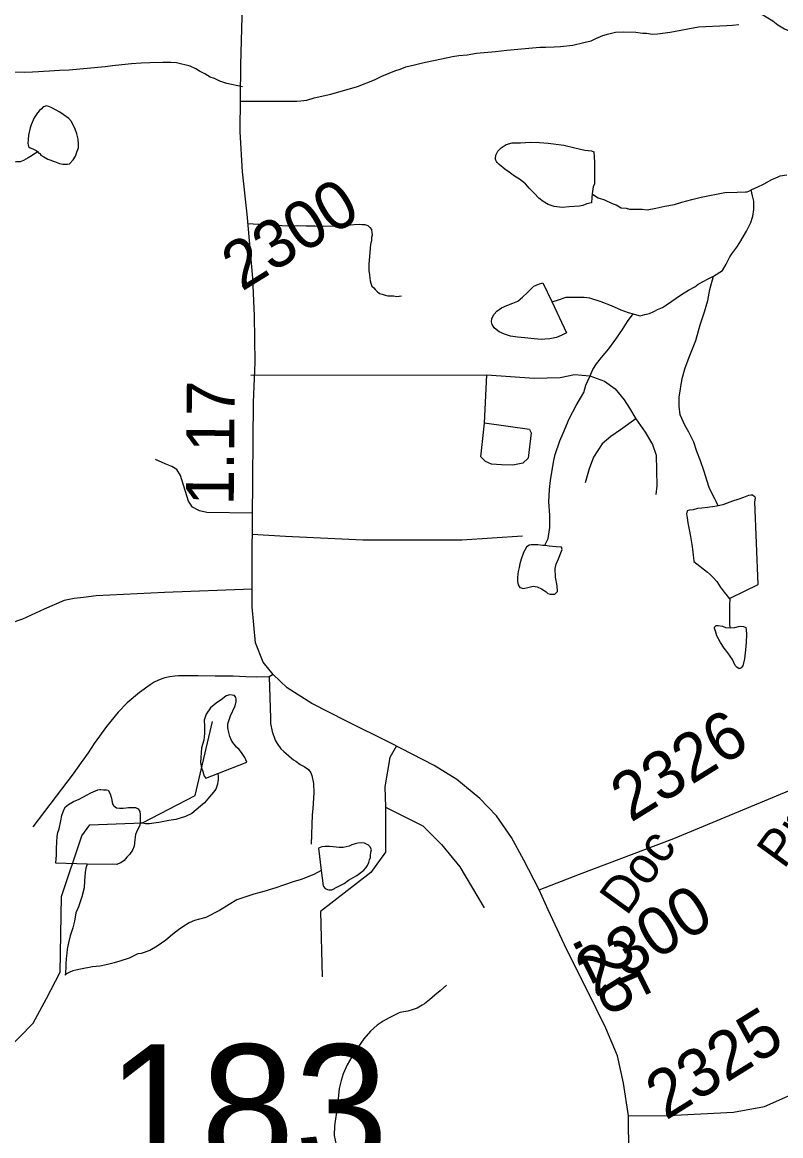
# Model space of a CAD drawing. Extents: x 2001466 to 31450019, y -30647475 to 847247.
# Drawn here: x 2175250 to 2179202, y 755442 to 761240 of the extents above; entities that cross this region are included whole.
import ezdxf

# ---------------------------------------------------------------- set-up
doc = ezdxf.new("R2010")
doc.units = 0
for name, color, linetype in [('Exist Hydrographic Misc Water Feature', 7, 'Continuous'), ('Exist Road Non-System Type 51', 7, 'Continuous'), ('Exist Road Secondary Mileage Hundredths English Label', 7, 'Continuous'), ('Exist Road Secondary Structure Standard Bridge Number Label', 7, 'Continuous'), ('Exist Road Secondary Type 51 Attributed', 7, 'Continuous'), ('Exist Road Secondary Type 51 Label', 7, 'Continuous'), ('Exist Road Secondary Type 51 Number Label', 7, 'Continuous')]:
    doc.layers.add(name, color=color, linetype=linetype)

msp = doc.modelspace()

# ---------------------------------------------------------------- linework, layer by layer
at = {"layer": 'Exist Hydrographic Misc Water Feature'}
for points in [[(2179000.1, 761330.1), (2179013.9, 761326.4), (2179037.8, 761314.7), (2179080.1, 761292.9), (2179118, 761273), (2179160.5, 761247.1), (2179188.1, 761227.5), (2179222.8, 761205.6), (2179250.5, 761193.7), (2179284.3, 761180), (2179328.6, 761162), (2179381.1, 761140.3), (2179474.8, 761090.8), (2179511.3, 761075.2), (2179547, 761069.4), (2179582.9, 761063.6), (2179603.2, 761059.7), (2179637.2, 761048)], [(2175331.5, 760565.9), (2175337.3, 760557.7), (2175341.4, 760555.9), (2175347.7, 760548), (2175363.3, 760540), (2175383.4, 760528), (2175417.6, 760514.3), (2175444.1, 760504.7), (2175462.1, 760500.7), (2175472, 760500.4), (2175485.9, 760500.8), (2175495.8, 760503), (2175515.7, 760523.1), (2175527.4, 760543.2), (2175537.2, 760568.9), (2175543.3, 760587), (2175543.3, 760604.9), (2175541.3, 760631.1), (2175534.7, 760658.9), (2175524.5, 760688.8), (2175508.7, 760718.8), (2175506.8, 760722.7), (2175492.5, 760738.7), (2175464.2, 760760.4), (2175446.1, 760772.4), (2175403.9, 760794.3), (2175388.1, 760801.9), (2175374.2, 760804.1), (2175367.8, 760802.2), (2175359.8, 760800.1), (2175350.2, 760789.8), (2175340.3, 760779.9), (2175330.3, 760767.7), (2175316.4, 760747.9), (2175312.3, 760741.6), (2175296.5, 760705.4), (2175290.9, 760689.7), (2175282.9, 760651.5), (2175280.9, 760629.5), (2175278.8, 760609.5), (2175281.3, 760601.5), (2175283.3, 760593.4), (2175291.5, 760585.7), (2175305.3, 760581.6), (2175309.6, 760579.8), (2175323.1, 760572), (2175331.5, 760565.9)], [(2178219.7, 760346.4), (2178217.8, 760328.4), (2178215.8, 760300.3), (2178192.2, 760294.1), (2178172.1, 760285.8), (2178154.1, 760282), (2178100.1, 760279.6), (2178064, 760275.3), (2178022.2, 760280.8), (2177990.2, 760290.9), (2177964, 760306.7), (2177941.8, 760324.6), (2177917.6, 760350.6), (2177891.4, 760376.5), (2177871.7, 760398.1), (2177841.2, 760422.2), (2177815.3, 760437.9), (2177787, 760459.6), (2177765.1, 760475.5), (2177735.1, 760499.5), (2177724.9, 760509.2), (2177720.8, 760515.5), (2177716.9, 760525.4), (2177716.7, 760529.5), (2177718.5, 760547.5), (2177728.6, 760569.4), (2177746.4, 760585.4), (2177772.5, 760603.4), (2177802.2, 760611.8), (2177846.1, 760612.1), (2177898.2, 760616.4), (2177946.3, 760614.4), (2177990.4, 760611), (2178072.3, 760599.4), (2178130.3, 760585.8), (2178182.2, 760573.9), (2178216.4, 760569.9), (2178228.1, 760566.1), (2178230.6, 760540.2), (2178232.8, 760510.2), (2178231.2, 760446.4), (2178231.2, 760398.1), (2178225.6, 760382.3), (2178219.7, 760346.4)], [(2175331.5, 760565.9), (2175309.6, 760551.8), (2175301.8, 760545.6), (2175281.5, 760533.7), (2175257.5, 760519.5), (2175239.9, 760513.2), (2175220, 760513.4), (2175203.8, 760511), (2175174, 760511), (2175145.7, 760516.9), (2175109.9, 760528.8), (2175087.3, 760536.7), (2175063.5, 760536.2), (2175045.5, 760538.1), (2175033.6, 760538.3), (2175029.9, 760538.1)], [(2179047.5, 760366.9), (2179067, 760376.9), (2179079.1, 760381.1), (2179115.4, 760399.2), (2179156.8, 760421.3), (2179189, 760435.5), (2179199, 760439.6), (2179234.9, 760446)], [(2178219.7, 760346.4), (2178231.4, 760338.5), (2178251.9, 760326.5), (2178284.1, 760314.7), (2178324.1, 760296.9), (2178345.6, 760288.8), (2178371.8, 760273), (2178396.2, 760271.4), (2178414.3, 760267.4), (2178461.9, 760267.5), (2178480.1, 760267.6), (2178506.3, 760263.7), (2178551.9, 760272.2), (2178597.8, 760282.3), (2178649.7, 760290.6), (2178687.8, 760302.7), (2178739.5, 760317.2), (2178787.5, 760329.4), (2178911.5, 760354.1), (2178975.1, 760356.2), (2179019.4, 760356.5), (2179027.6, 760356.9), (2179035.4, 760361), (2179047.5, 760366.9)], [(2178852.1, 759917.7), (2178899.6, 759948.2), (2178917.7, 759980), (2178937.6, 760018.4), (2178947, 760034.4), (2178973, 760068.6), (2178989, 760092.5), (2179024.5, 760152.9), (2179046.5, 760197), (2179057.9, 760231), (2179061.8, 760264.8), (2179061.8, 760294.9), (2179061.6, 760308.7), (2179055.3, 760336.9), (2179047.5, 760366.9)], [(2178432.9, 759721.4), (2178439.1, 759719.7), (2178469.2, 759711.9), (2178494.9, 759717.8), (2178518.9, 759724.3), (2178541, 759734.3), (2178560.9, 759744.3), (2178586.7, 759754.6), (2178607, 759768.6), (2178684.5, 759823), (2178722.3, 759845.3), (2178754, 759863.1), (2178772.3, 759875.4), (2178797.9, 759889.8), (2178823.8, 759903.7), (2178845.7, 759913.8), (2178852.1, 759917.7)], [(2178876.5, 758722.2), (2178866.2, 758744.4), (2178858.2, 758758.2), (2178832, 758812.1), (2178818, 758856), (2178803.7, 758899.9), (2178785.2, 758955.8), (2178765.1, 759005.5), (2178748.9, 759053.4), (2178724.3, 759105.4), (2178702.4, 759141.2), (2178678.2, 759195.1), (2178673.9, 759241.2), (2178673.5, 759287.1), (2178688.8, 759385), (2178704.6, 759441), (2178728, 759505.2), (2178759.8, 759583.6), (2178783.4, 759663.6), (2178804.9, 759731.8), (2178822.5, 759791.5), (2178832.2, 759847.7), (2178852.1, 759917.7)], [(2178008.9, 759785.1), (2178085.6, 759623.4), (2178057.7, 759609.4), (2178033.9, 759599.2), (2177999.9, 759591.3), (2177974, 759589.2), (2177954.1, 759588.9), (2177899.8, 759592.7), (2177868.2, 759596.3), (2177830.3, 759600.4), (2177794.2, 759605.8), (2177763.9, 759615.6), (2177735.8, 759627.6), (2177720, 759639.8), (2177709.9, 759649.4), (2177699.5, 759665.6), (2177695.6, 759679.6), (2177697.6, 759697.5), (2177709.3, 759719.7), (2177723, 759735.4), (2177747, 759753.8), (2177775.3, 759765.6), (2177807.1, 759777.9), (2177832.5, 759788.3), (2177856.7, 759808.1), (2177882.4, 759832.6), (2177896.7, 759846.3), (2177916.6, 759866.4), (2177940.4, 759876.6), (2177962.3, 759883), (2178008.9, 759785.1)], [(2178008.9, 759785.1), (2178016.9, 759785.1), (2178045, 759795.5), (2178084.8, 759807.7), (2178122.7, 759807.7), (2178178.9, 759808.1), (2178206.8, 759804.3), (2178265, 759786.6), (2178318.7, 759765.1), (2178369, 759743.2), (2178407.1, 759729.4), (2178432.9, 759721.4)], [(2177974.2, 758515.4), (2177975.9, 758523.2), (2177990, 758551.5), (2177999.7, 758609.3), (2177998.8, 758673.5), (2177994.7, 758743.5), (2177998.2, 758807.5), (2178002.1, 758853.6), (2178009.7, 758897.4), (2178019.3, 758957.6), (2178027.3, 758989.7), (2178050.7, 759059.5), (2178068.6, 759099.9), (2178100.3, 759175.8), (2178135.8, 759243.8), (2178175.8, 759312.1), (2178187.3, 759350.5), (2178207, 759394.6), (2178223, 759432.3), (2178242.4, 759460.6), (2178268.3, 759494.8), (2178306.2, 759539), (2178343.9, 759589.2), (2178377.8, 759639.3), (2178403.4, 759681.3), (2178432.9, 759721.4)], [(2178939.2, 758240.9), (2179084.8, 758311.8), (2179068.2, 758743.5), (2179070.4, 758761.5), (2179070, 758769.6), (2179063.9, 758771.3), (2179056.1, 758777.4), (2179047.9, 758777.4), (2179034.2, 758775.4), (2179008.1, 758765.1), (2178978.4, 758755), (2178950.3, 758746.7), (2178900.7, 758726.6), (2178876.5, 758722.2)], [(2178876.5, 758722.2), (2178858.8, 758718.4), (2178820.3, 758714), (2178790.8, 758710), (2178768.6, 758707.7), (2178746.5, 758701.7), (2178727, 758699.4), (2178714.7, 758695.5), (2178710.8, 758679.5), (2178714.7, 758659.4), (2178719, 758633.7), (2178725.1, 758599.4), (2178731.5, 758561.5), (2178739.9, 758519.7), (2178743.8, 758481.8), (2178745.8, 758463.7), (2178748.1, 758453.6), (2178750.4, 758431.7), (2178820.5, 758376.1), (2178836.5, 758362.3), (2178852.7, 758346.5), (2178868.7, 758328.6), (2178886.5, 758300.8), (2178907, 758272.6), (2178922.8, 758252.7), (2178929.2, 758246.9), (2178935.5, 758237), (2178939.2, 758240.9)], [(2177974.2, 758515.4), (2177962.3, 758515.1), (2177936.1, 758519.1), (2177920.1, 758519.1), (2177902.1, 758519), (2177892, 758516.9), (2177878.1, 758506.8), (2177862.3, 758478.7), (2177850.4, 758444.9), (2177842.4, 758420.5), (2177838.7, 758400.8), (2177835, 758380.7), (2177832.5, 758366.8), (2177831.3, 758348.8), (2177830.9, 758328.5), (2177833.6, 758310.7), (2177843.4, 758296.6), (2177861.3, 758290.7), (2177891.4, 758299.1), (2177913.3, 758303.1), (2177933.2, 758299.3), (2177955.4, 758289.5), (2177969.3, 758281.3), (2177979.4, 758273.6), (2177989.6, 758265.6), (2178001.3, 758261.4), (2178025.5, 758261.8), (2178039.2, 758275.9), (2178037.2, 758305.9), (2178028.6, 758349.8), (2178026.5, 758395.5), (2178032.3, 758417.7), (2178044.4, 758446), (2178060.2, 758485.8), (2178064.3, 758494.1), (2178060.2, 758506.1), (2178032.1, 758507.9), (2177996, 758511.3), (2177974.2, 758515.4)], [(2178938.2, 758086.9), (2178938, 758108.9), (2178938, 758126.7), (2178937.6, 758154.8), (2178937.6, 758180.7), (2178937.6, 758210.8), (2178939.2, 758228.8), (2178939.2, 758240.9)], [(2178938.2, 758086.9), (2178964, 758089.1), (2178982.1, 758093.3), (2178992.3, 758095.4), (2179008.1, 758093.4), (2179019.8, 758087.6), (2179022.1, 758077.5), (2179024.5, 758051.6), (2179022.5, 758009.3), (2179018.8, 757971.3), (2179013.2, 757925.5), (2179005, 757889.4), (2178995.4, 757877.5), (2178985.3, 757873.3), (2178973.3, 757881.3), (2178965, 757891), (2178951.3, 757921), (2178927.1, 757956.8), (2178908.5, 757980.7), (2178888.4, 758010.5), (2178870.3, 758044.5), (2178864.2, 758064.4), (2178857.8, 758084.5), (2178858, 758090.5), (2178866.2, 758098.6), (2178875.9, 758098.8), (2178898.2, 758094.6), (2178913.8, 758089), (2178938.2, 758086.9)], [(2176269.2, 757328.2), (2176421, 757386.8), (2176410.9, 757411), (2176392.7, 757436.9), (2176380.6, 757452.9), (2176366.2, 757464.8), (2176354.5, 757480.4), (2176342.2, 757496.4), (2176332.2, 757520.3), (2176326, 757542.3), (2176321.9, 757566.4), (2176321.9, 757586.3), (2176335.7, 757628.4), (2176347.4, 757654.7), (2176359.2, 757680.5), (2176365.2, 757702.7), (2176364.8, 757716.5), (2176363.1, 757724.5), (2176356.8, 757734.4), (2176332.8, 757738.4), (2176313.1, 757732.4), (2176293, 757716), (2176260.8, 757694.1), (2176231.3, 757669.8), (2176209.4, 757637.8), (2176197.7, 757605.9), (2176199.9, 757573.5), (2176200.1, 757535.8), (2176196, 757501.5), (2176184.7, 757461.8), (2176178.8, 757385.7), (2176185.2, 757357.5), (2176191.3, 757337.9), (2176195.2, 757325.6), (2176199.1, 757313.6), (2176207.3, 757303.8), (2176269.2, 757328.2)], [(2175376.3, 756156.9), (2175448, 756293.4), (2175454.1, 756686.9), (2175561.2, 757002.9), (2175602, 757061.1), (2175877.2, 757071.8), (2176151.1, 757213.8), (2176241.1, 757599.1)], [(2176269.2, 757328.2), (2176271.3, 757310), (2176271.1, 757294.2), (2176269.8, 757286.3), (2176267.6, 757272.1), (2176259.8, 757246), (2176246.1, 757229.9), (2176226, 757206.1), (2176200.1, 757175.9), (2176180, 757157.9), (2176134.5, 757119.3), (2176100.9, 757103.3), (2176050.4, 757089), (2176014.6, 757082.7), (2175962.7, 757072.7), (2175948.7, 757070.3), (2175912.8, 757066), (2175892.8, 757066.2), (2175876.8, 757069.9), (2175864.9, 757072.1)], [(2175588, 756856.3), (2175426.1, 756861.3), (2175428.1, 756903.6), (2175428.1, 756939.4), (2175431.6, 757001.3), (2175435.3, 757021.4), (2175443.1, 757039.7), (2175450.9, 757081.5), (2175456.8, 757109.8), (2175466.4, 757139.6), (2175476.5, 757153.9), (2175492.1, 757165.7), (2175518.1, 757182.1), (2175546.4, 757194), (2175566.1, 757204.1), (2175588, 757216.1), (2175607.9, 757226.5), (2175620, 757232.4), (2175643.8, 757242.6), (2175653.9, 757244.7), (2175659.8, 757244.6), (2175673.6, 757242.9), (2175689.8, 757242.9), (2175698, 757240.9), (2175707.8, 757221.2), (2175714.2, 757205.2), (2175716.4, 757189), (2175718.3, 757177), (2175722.1, 757167.1), (2175726.3, 757161.2), (2175734.2, 757155.1), (2175742.2, 757149.4), (2175756.4, 757147.3), (2175776.3, 757147.5), (2175792.3, 757149.5), (2175804.2, 757151.4), (2175816.1, 757151.6), (2175832.3, 757151.6), (2175840.3, 757151.6), (2175854.4, 757143.8), (2175862.6, 757130), (2175864.7, 757113.9), (2175864.9, 757079.8), (2175864.9, 757072.1)], [(2175864.9, 757072.1), (2175863, 757057.8), (2175851.3, 757033.9), (2175840.9, 757009.9), (2175837.6, 756981.7), (2175833.5, 756949.9), (2175825.5, 756927.9), (2175809.9, 756905.5), (2175795.8, 756891.5), (2175782, 756875.7), (2175763.8, 756863.4), (2175750, 756857.4), (2175743.9, 756853.4), (2175588, 756856.3)], [(2176807.7, 756823.2), (2176818.2, 756743.4), (2176820.4, 756739.4), (2176828.2, 756729.7), (2176840.3, 756723.4), (2176848.5, 756721.7), (2176862.6, 756721.6), (2176892.6, 756737.8), (2176928.3, 756755.9), (2176950, 756772.1), (2176994.1, 756796.3), (2177007.6, 756806.4), (2177029.8, 756824.6), (2177041.9, 756838.6), (2177049.5, 756848.8), (2177055.6, 756864.9), (2177059.7, 756878.9), (2177065.4, 756890.6), (2177065.4, 756900.8), (2177067.1, 756918.8), (2177069.5, 756931), (2177062.8, 756946.9), (2177054.8, 756954.7), (2177041.2, 756962.4), (2177033, 756964.4), (2177018.9, 756966.6), (2176999, 756964.3), (2176985.1, 756962.4), (2176967, 756956.2), (2176952.9, 756950.2), (2176923.1, 756942.1), (2176901.4, 756941.8), (2176871.1, 756945.6), (2176851.4, 756947.7), (2176829.2, 756947.4), (2176811.4, 756945.2), (2176793.3, 756939), (2176807.7, 756823.2)], [(2175588, 756856.3), (2175582.3, 756834.5), (2175578.6, 756812.3), (2175574.7, 756768.3), (2175572.9, 756732.5), (2175561, 756686.4), (2175543.3, 756634.3), (2175529.6, 756602.3), (2175521.8, 756558.1), (2175514, 756523.9), (2175500.3, 756482.2), (2175490.9, 756445.9), (2175484.7, 756414), (2175482.6, 756392), (2175479, 756364.1), (2175477.1, 756336), (2175477.1, 756320.2), (2175475.3, 756292.1), (2175473.4, 756278.2)], [(2176807.7, 756823.2), (2176770, 756801.4), (2176704.3, 756776.8), (2176662.3, 756764.5), (2176612.1, 756746.1), (2176572.3, 756731.9), (2176508.5, 756713.5), (2176456.9, 756699.4), (2176404.8, 756682.9), (2176368.9, 756670.9), (2176329.1, 756646.5), (2176277.4, 756614.2), (2176207.7, 756578.1), (2176173.5, 756569.9), (2176147.4, 756561.6), (2176119.5, 756549.6), (2176087.8, 756529.3), (2176063.8, 756513.4), (2176033.8, 756489.2), (2175998.6, 756460.8), (2175954.1, 756428.6), (2175914.7, 756406.6), (2175870.8, 756390.1), (2175852.6, 756388), (2175806.8, 756366.1), (2175758.9, 756351.4), (2175729.1, 756341.3), (2175687.1, 756331), (2175655.1, 756324.9), (2175617, 756320.9), (2175553.2, 756308.3), (2175529.2, 756304.2), (2175513.2, 756300.1), (2175499.1, 756294.2), (2175481.2, 756284.3), (2175473.4, 756278.2)], [(2177461.2, 756225.1), (2177427.2, 756197), (2177399.3, 756172.8), (2177371.6, 756148.6), (2177345.5, 756128.6), (2177333.7, 756120.7), (2177308, 756106.3), (2177281.6, 756096.5), (2177259.8, 756090.1), (2177218, 756083.8), (2177190.1, 756069.8), (2177162.2, 756055.7), (2177130.2, 756037.4), (2177100.1, 756017.2), (2177064.4, 755986.9), (2177030.6, 755947), (2176979.1, 755872.5), (2176943.8, 755810.4), (2176922.1, 755764.3), (2176912.3, 755728.4), (2176902.2, 755688.2), (2176896.5, 755634.3), (2176890.9, 755582.4), (2176885, 755542.3), (2176877.6, 755492.3), (2176875.6, 755442.3), (2176885.8, 755394.1)], [(2174048.1, 755003.3), (2174180.2, 755187.6), (2174354, 755321.8), (2174586.2, 755546.7), (2174802.1, 755683.3), (2175085.1, 755802.1), (2175308.1, 756027.2), (2175376.3, 756156.9)]]:
    msp.add_lwpolyline(points, dxfattribs=at)
at = {"layer": 'Exist Road Non-System Type 51'}
for p, q in [((2176441.8, 759402.7), (2177670.6, 759404.4)), ((2177658.7, 759152.6), (2177670.6, 759404.4)), ((2177894.1, 759119.2), (2177658.7, 759152.6)), ((2176557, 757843.4), (2176536.2, 757830.6))]:
    msp.add_line(p, q, dxfattribs=at)
for points in [[(2176391.6, 760829.7), (2176680.3, 760829.6), (2176702.4, 760831.1), (2176732.4, 760834.7), (2176770.7, 760845.9), (2176858.9, 760866.5), (2176997.7, 760906.3), (2177086.2, 760940.6), (2177124.5, 760960), (2177162.9, 760975.5), (2177191.1, 760986.9), (2177219.3, 760996.5), (2177249.3, 761008.1), (2177293.5, 761019.2), (2177335.7, 761028.5), (2177492.4, 761061.9), (2177524.5, 761067.4), (2177568.6, 761070.7), (2177616.7, 761079.9), (2177716.9, 761088.1), (2177775, 761095.3), (2177947.3, 761110.4), (2177979.3, 761109.7), (2178021.4, 761113), (2178055.4, 761114.5), (2178119.5, 761121.4), (2178176.2, 761134.9), (2178214, 761143.9), (2178238.2, 761155.4), (2178276.3, 761170.8), (2178306.5, 761180.4), (2178340.7, 761187.7), (2178382.7, 761191), (2178446.6, 761187.9), (2178470.8, 761185.6), (2178484.7, 761183.3), (2178502.7, 761183), (2178534.6, 761178.5), (2178560.7, 761180), (2178626.8, 761189), (2178773.4, 761216.4), (2178921.5, 761224), (2178951.5, 761225.6), (2178983.6, 761228.9)], [(2176397.5, 760904.2), (2176315.7, 760921.6), (2176279.9, 760934.2), (2176252, 760946.7), (2176230.2, 760955), (2176202.5, 760971.5), (2176174.6, 760985.9), (2176154.9, 760998.3), (2176125.1, 761010.9), (2176053.3, 761028), (2176025.3, 761030.6), (2175983.4, 761031.2), (2175915.3, 761028.4), (2175869.3, 761027.2), (2175819.2, 761024), (2175769.1, 761018.8), (2175721, 761013.6), (2175682.9, 761008.2), (2175494.6, 760991.5), (2175444.6, 760988.3), (2175392.5, 760985.1), (2175360.5, 760983.6), (2175334.5, 760982.1), (2175304.4, 760980.6), (2175260.4, 760979.3), (2175149.7, 760982.3)], [(2176424.8, 760192.1), (2176603.7, 760182.6), (2176729.6, 760180.4), (2176775.6, 760179.7), (2176821.6, 760178.9), (2176911.6, 760179.5), (2176943.6, 760182.8), (2176979.7, 760186.3), (2177005.7, 760188), (2177021.7, 760187.6), (2177035.7, 760187.4), (2177051.8, 760181), (2177061.6, 760171), (2177069.4, 760160.9), (2177069.3, 760156.9), (2177071.1, 760146.8), (2177072.9, 760130.8), (2177070.7, 760118.8), (2177070.4, 760104.8), (2177064.2, 760083), (2177056.5, 759980.9), (2177055.8, 759947), (2177059.5, 759924.9), (2177061.1, 759906.9), (2177062.9, 759892.8), (2177066.8, 759880.7), (2177072.5, 759866.6), (2177082.3, 759856.4), (2177090.1, 759848.5), (2177100.1, 759838.3), (2177111.9, 759828), (2177125.8, 759823.7), (2177141.7, 759819.6), (2177155.7, 759815.3), (2177171.6, 759815), (2177185.6, 759814.7), (2177201.6, 759812.6), (2177225.7, 759816.1)], [(2177670.6, 759404.4), (2177917.9, 759387.2), (2178053, 759390.6), (2178127.4, 759405.8), (2178208.5, 759399), (2178284.5, 759370.3), (2178340.2, 759331.4), (2178387.5, 759273.9), (2178414.6, 759230), (2178446.7, 759174.2)], [(2177858.1, 758944.3), (2177807.4, 758934.1), (2177748.3, 758935.8), (2177695.9, 758939.2), (2177663.8, 758953.1), (2177640.2, 758976.7), (2177658.7, 759152.6)], [(2178446.7, 759174.2), (2178367.3, 759118.4), (2178316.6, 759082.9), (2178272.7, 759044), (2178227, 758974.7), (2178205.1, 758913.9), (2178183, 758842.1)], [(2178446.7, 759174.2), (2178495.6, 759104.9), (2178534.5, 759040.6), (2178553.1, 758984.9), (2178557.7, 758826.2), (2178551.7, 758780.4)], [(2177894.1, 759119.2), (2177902, 759101.5), (2177886.8, 758969.6), (2177858.1, 758944.3)], [(2176450.3, 758684.1), (2176211.9, 758686.3), (2176173.6, 758695.3), (2176137.6, 758715.6), (2176116.2, 758746), (2176075.6, 758879.1), (2176055.3, 758910.6), (2176029.4, 758926.4), (2175995.6, 758939.9), (2175944.9, 758963.6)], [(2176449.1, 758573.5), (2176621.8, 758564.7), (2177025.2, 758544.4), (2177541, 758545.5), (2177856.3, 758565.8)], [(2176447.6, 758288), (2175991.8, 758269.8), (2175636.2, 758252.7), (2175568.7, 758245.3), (2175520.9, 758239.2), (2175468.2, 758228.1), (2175364, 758183.9), (2175252.4, 758132.4), (2175117.5, 758085.8)], [(2176536.2, 757830.6), (2176470, 757829.3), (2176414.8, 757830.6), (2176349.8, 757834.2), (2176255.4, 757835.5), (2176167.1, 757836.7), (2176094.8, 757836.7), (2176065.3, 757836.7), (2176045.7, 757834.2), (2176018.7, 757830.6), (2175993, 757825.7), (2175978.3, 757820.7), (2175957.4, 757812.2), (2175937.8, 757803.6), (2175917, 757790.1), (2175860.6, 757749.6), (2175796.8, 757695.6), (2175750.7, 757647.7), (2175689.4, 757572.9), (2175625.6, 757484.6), (2175593.8, 757435.5), (2175558, 757384.9), (2175516.3, 757326), (2175305.4, 757050)], [(2176536.2, 757830.6), (2176544, 757615.9), (2176543.7, 757603.9), (2176543.6, 757587.9), (2176552, 757546), (2176568, 757501.4), (2176577.9, 757483.4), (2176597.3, 757457), (2176613, 757442.7), (2176638.8, 757420.4), (2176652.5, 757408.1), (2176664.3, 757399.9), (2176676.4, 757391.6), (2176699.2, 757375.6), (2176719.8, 757364.9), (2176741.5, 757348.5), (2176753.9, 757330.8), (2176759, 757317.5), (2176768.2, 757275.8), (2176769.6, 757227.9), (2176764.1, 757146.1), (2176761.6, 757112.1), (2176756.5, 756959.2)], [(2177200, 757471.7), (2177166.1, 757412), (2177139.8, 757259), (2177143.3, 757151.8)], [(2177143.3, 757151.8), (2177143.3, 756919), (2177065.8, 756812.3), (2176804, 756608.6), (2176813.7, 756269.1)], [(2177143.3, 757151.8), (2177337.3, 757054.8), (2177434.2, 756957.8), (2177531.2, 756841.4), (2177657.2, 756628)]]:
    msp.add_lwpolyline(points, dxfattribs=at)
at = {"layer": 'Exist Road Secondary Type 51 Attributed'}
for points in [[(2177942.9, 756721.9), (2177864.4, 756876.9), (2177799.6, 756994.2), (2177720.6, 757107.3), (2177634.7, 757198.4), (2177515.5, 757296.8), (2177397.2, 757370.1), (2177167.5, 757488.4), (2176940.5, 757600.5), (2176758.4, 757692.6), (2176631.3, 757774.3), (2176557, 757843.4), (2176505.7, 757908.3), (2176465.9, 758008.8), (2176447.6, 758196.3), (2176447.6, 758446.5), (2176452.3, 758864.3), (2176456, 759262.2), (2176463.3, 759467.5), (2176460.7, 759711.5), (2176452.3, 759908.3), (2176421.5, 760240.3), (2176398.4, 760461.2), (2176386.4, 760669.6), (2176389.6, 761018.3), (2176398.4, 761333.5)], [(2177942.9, 756721.9), (2178154.3, 756803.6), (2178646.1, 756990), (2179272.9, 757249.7), (2179871.4, 757507.3), (2180406.1, 757731.4), (2180810, 757890.5), (2181213.9, 758058.1), (2181349.9, 758106.2), (2181554, 758158.6)], [(2178408.5, 755546), (2178615.7, 755547.1), (2178956.9, 755563.8), (2179118, 755593.1), (2179239.4, 755647.6), (2179333.5, 755708.3), (2179434, 755806.7), (2179554.3, 755942.9), (2179659, 756072.7), (2179757.3, 756156.5), (2179960.3, 756301), (2180178, 756470.6), (2180417.6, 756650.7), (2180526.4, 756761.7), (2180677.1, 756962.8), (2180877, 757279), (2181105.1, 757630.8), (2181267.3, 757873.8), (2181394.9, 758039.2), (2181554, 758158.6)], [(2178408.5, 755546), (2178383.4, 755714.6), (2178352, 755857), (2178291.4, 756001.5), (2178190.9, 756206.7), (2178088.4, 756409.9), (2177991, 756617.2), (2177942.9, 756721.9)], [(2177999.4, 753024.5), (2178020.3, 753112.5), (2178046.5, 753244.4), (2178116.1, 753439.2), (2178190.4, 753659.1), (2178320.7, 753995.2), (2178368.8, 754146), (2178409.1, 754295.7), (2178414.3, 754386.8), (2178415.3, 754505.2), (2178414.8, 754826.6), (2178411.7, 755047.6), (2178411.2, 755349.1), (2178408.5, 755546)]]:
    msp.add_lwpolyline(points, dxfattribs=at)

# ---------------------------------------------------------------- texts
at = {"layer": 'Exist Road Secondary Mileage Hundredths English Label'}
for s, rotation, p in [('1.17', 89.47268, (2176352.2, 758722.6)), ('.25', 296.45171, (2178108.1, 756467.7))]:
    msp.add_text(s, height=250, rotation=rotation, dxfattribs=at).set_placement(p)
at = {"layer": 'Exist Road Secondary Structure Standard Bridge Number Label'}
msp.add_text('183', height=656.17, dxfattribs=at).set_placement((2175693.1, 755260.8))
at = {"layer": 'Exist Road Secondary Type 51 Label'}
for s, p in [('Proctor', (2179219.3, 756825.3)), ('Doc', (2178399.6, 756581.8))]:
    msp.add_text(s, height=190, rotation=54.05691, dxfattribs=at).set_placement(p)
at = {"layer": 'Exist Road Secondary Type 51 Number Label'}
for s, p in [('2300', (2176394.1, 759835.8)), ('2326', (2178421, 757069.9)), ('2300', (2178236.2, 756158)), ('2325', (2178603.7, 755519.2))]:
    msp.add_text(s, height=250, rotation=31.91803, dxfattribs=at).set_placement(p)

doc.saveas('drawing.dxf')
